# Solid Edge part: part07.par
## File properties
Accuracy: 0.99
Author: CADCIM
Template: Normal.par
Last saved by: Rajat Kamboj
Revision: 7
Application: Solid Edge
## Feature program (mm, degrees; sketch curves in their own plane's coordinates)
sketch for "unnamed Protrusion 1" #1 plane through (0, 0, 0) normal (0, 0, 1) x-axis (1, 0, 0)
  circle centre (17.5, 12.5) radius 2.5
sketch for "unnamed Protrusion 1" #2 plane through (0, 0, 0) normal (0, 0, 1) x-axis (1, 0, 0)
  circle centre (17.5, -12.5) radius 2.5
sketch for "unnamed Protrusion 1" #3 plane through (0, 0, 0) normal (0, 0, 1) x-axis (1, 0, 0)
  line (-17.5, 2.5) -> (-22.5, 2.5)
  line (-22.5, 2.5) -> (-22.5, 5.5)
  arc centre (-20.5, 5.5) radius 2 from (-22.5, 5.5) to (-20.5, 7.5) cw
  line (-20.5, 7.5) -> (10.5, 7.5)
  arc centre (10.5, 9.5) radius 2 from (10.5, 7.5) to (12.5, 9.5) ccw
  line (12.5, 9.5) -> (12.5, 12.5)
  arc centre (17.5, 12.5) radius 5 from (12.5, 12.5) to (22.5, 12.5) cw
  line (22.5, 12.5) -> (22.5, -12.5)
  arc centre (17.5, -12.5) radius 5 from (12.5, -12.5) to (22.5, -12.5) ccw
  line (12.5, -9.5) -> (12.5, -12.5)
  arc centre (10.5, -9.5) radius 2 from (10.5, -7.5) to (12.5, -9.5) cw
  line (-20.5, -7.5) -> (10.5, -7.5)
  arc centre (-20.5, -5.5) radius 2 from (-22.5, -5.5) to (-20.5, -7.5) ccw
  line (-22.5, -2.5) -> (-22.5, -5.5)
  line (-17.5, -2.5) -> (-22.5, -2.5)
  arc centre (-17.5, 0) radius 2.5 from (-17.5, 2.5) to (-17.5, -2.5) cw
  dimension (linear) = 22.5
  dimension (linear) = 17.5
extrude "unnamed Protrusion 1" add finite 5 along +normal
sketch for "ExtrudedProtrusion_2" #1 plane through (6.5901, 0, 20.9099) normal (0.707107, 0, 0.707107) x-axis (0, 1, 0)
  circle centre (0, -5.5) radius 3.75
sketch for "ExtrudedProtrusion_2" #2 plane through (6.5901, 0, 20.9099) normal (0.707107, 0, 0.707107) x-axis (0, 1, 0)
  line (-7.5, -22.5) -> (-7.5, -5.5)
  arc centre (0, -5.5) radius 7.5 from (7.5, -5.5) to (-7.5, -5.5) ccw
  line (7.5, -5.5) -> (7.5, -22.5)
  line (7.5, -22.5) -> (-7.5, -22.5)
  dimension (linear) = 7.5
extrude "ExtrudedProtrusion_2" add through along -normal
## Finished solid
Body 1: solid body, 26 faces, 64 edges, 38 vertices.
  Faces by surface: plane 15, cylinder 11
  Edges by curve: line 42, circle 20, ellipse 2
Bounding box of the edges (mm): 45.000 x 35.000 x 22.324, from (-22.5, -17.5, 0) to (22.5, 17.5, 22.3241).
Cylindrical faces by radius (mm): R2 x4, R2.5 x3, R3.75 x1, R5 x2, R7.5 x1
Planar faces by outward normal: +x 1, +y 2, +z 4, -x 4, -y 2, -z 1, oblique 1
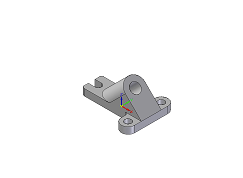
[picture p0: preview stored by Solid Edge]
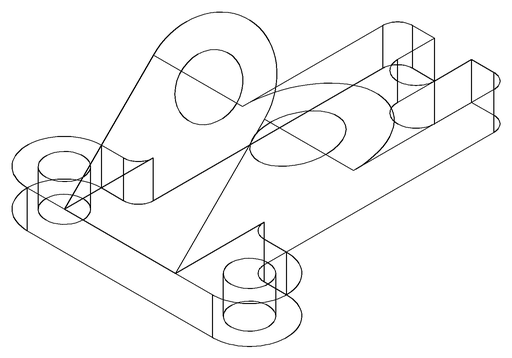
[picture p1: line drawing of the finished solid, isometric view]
